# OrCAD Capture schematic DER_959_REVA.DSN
size B; title: DER-959; rev: A
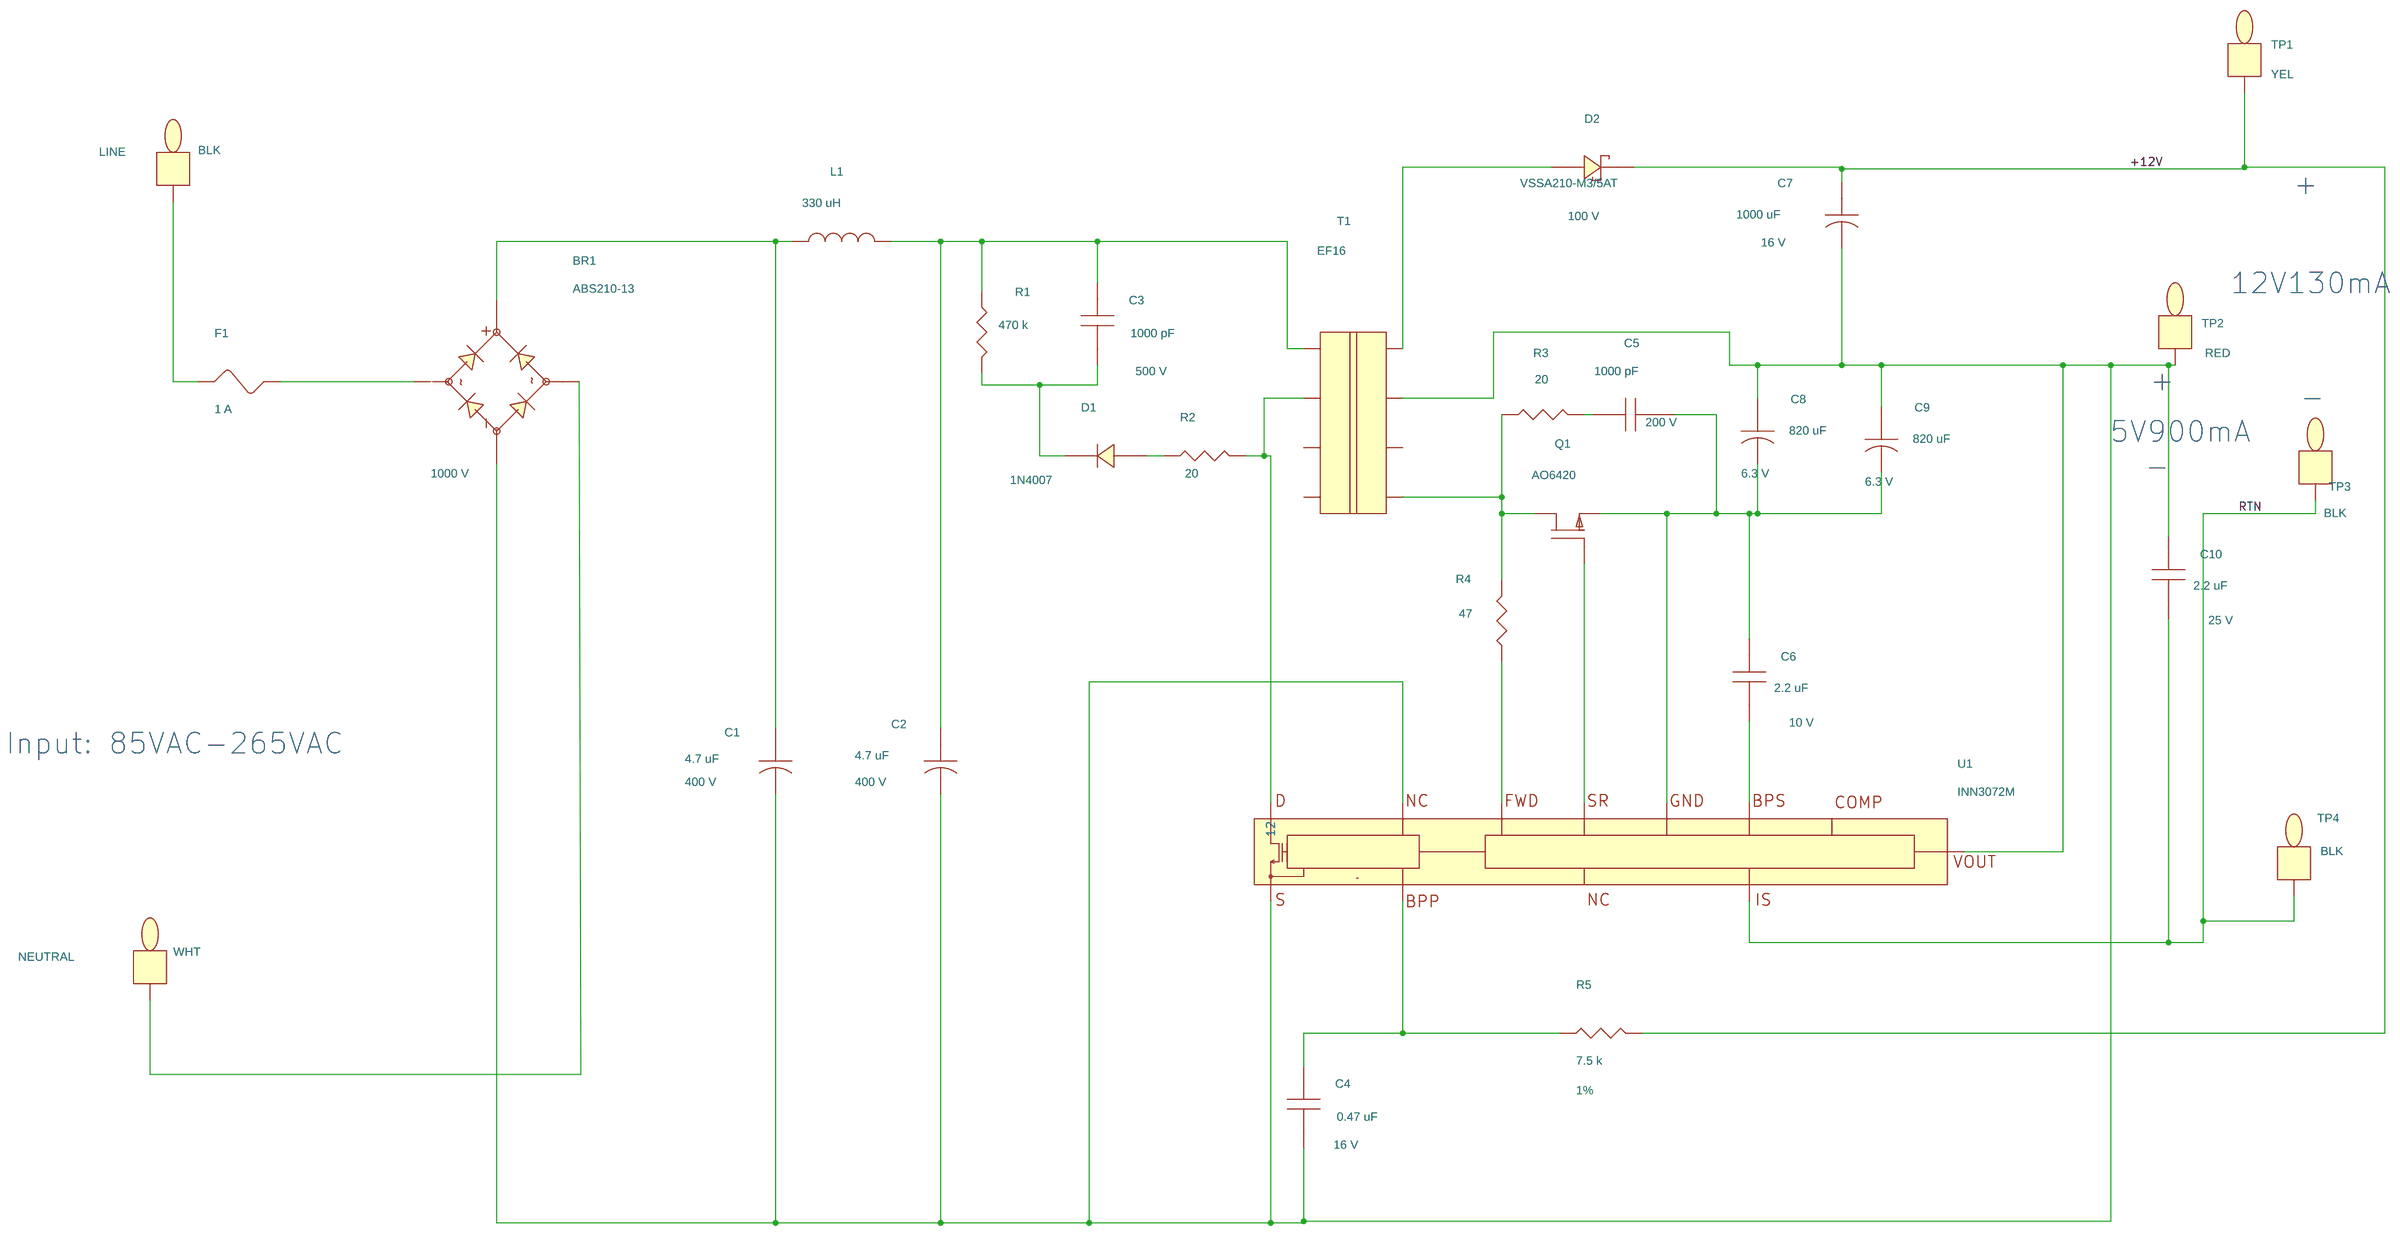
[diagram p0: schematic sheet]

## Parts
BR1  ABS210-13  [pismd_SOPA-4]
C1  4.7 uF  [pipolcapclyd320ls140030]
C2  4.7 uF  [pipolcapclyd320ls140030]
C3  1000 pF  [pismc0805]
C4  0.47 uF  [pismc0603]
C5  1000 pF  [pismc0603]
C6  2.2 uF  [pismc0603]
C7  1000 uF  [pipolcapclyd320ls140030]
C8  820 uF  [pi_polcap_d320ls200d030]
C9  820 uF  [pi_polcap_d320ls200d030]
C10  2.2 uF  [pismc0805]
D1  1N4007  [pidv200x110x040do41]
D2  VSSA210-M3/5AT  [pismdo214ac12]
F1  1 A  [pi_rst_microfuse]
L1  330 uH  [pichoketokinvd216h413ls098d030]
LINE  BLK  [pitpkeystone100x100]
NEUTRAL  WHT  [pitpkeystone100x100]
Q1  AO6420  [pismsot236_short1256]
R1  470 k  [pismr0805]
R2  20  [pismr0805]
R3  20  [pismr0603]
R4  47  [pismr0603]
R5  7.5 k  [pismr0603]
T1  EF16  [pibobbinEF16V8P]
TP1  YEL  [pitpkeystone100x100]
TP2  RED  [pitpkeystone100x100]
TP3  BLK  [pitpkeystone100x100]
TP4  BLK  [pitpkeystone100x100]
U1  INN3072M  [PI_SM_MinSOP16A_1]

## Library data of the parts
BR1 = DIODE_BRIDGE_+~~-: ALT_SYMBOLS: pismd_SOPA-4a,pi_sm_soic4_slot; Disp_Voltage: 1000 V; FPLIST: pismd_SOPA-4,pismd_SOPA-4a,pi_sm_soic4_slot; Part Number: 15-01254-00
C1 C2 = CAP_POL: ALT_SYMBOLS: pipolcapclyd320ls140030h; Disp_Voltage: 400 V; FPLIST: pipolcapclyd320ls140030,pipolcapclyd320ls140030430h,pipolcapclyd320ls140030h; Part Number: 20-00567-00; Voltage: 400 V
C3 = CAP_NP: Disp_Voltage: 500 V; Part Number: 20-09036-00; Voltage: 500 V
C4 = CAP_NP: Disp_Voltage: 16 V; Part Number: 20-08990-00; Voltage: 16 V
C5 = CAP_NP: Disp_Voltage: 200 V; Part Number: 20-09194-00; Voltage: 200 V
C6 = CAP_NP: ALT_SYMBOLS: pismc0603_1; Disp_Voltage: 10 V; FPLIST: pismc0603,pismc0603_1; Part Number: 20-08740-00; Voltage: 10V
C7 = CAP_POL: ALT_SYMBOLS: pipolcapclyd320ls140d30h750; Disp_Voltage: 16 V; FPLIST: pipolcapclyd320ls140030,pipolcapclyd320ls140d30h750; Part Number: 20-08710-00; Voltage: 16 V
C8 C9 = CAP_POL: Disp_Voltage: 6.3 V; Part Number: 20-01648-00; Voltage: 6.3 V
C10 = CAP_NP: Disp_Voltage: 25 V; Part Number: 20-01429-00; Voltage: 25 V
D1 = DIODE: ALT_SYMBOLS: pidax475x125040do41,pidv200x110x040do41wbead,pidax390x125040do41; FPLIST: pidv200x110x040do41,pidax475x125040do41,pidv200x110x040do41wbead,pidax390x125040do41; Part Number: 15-00623-00
D2 = DIODE_SCHOTTKY: Disp_Voltage: 100 V; Part Number: 15-01759-00
F1 = FUSE: ALT_SYMBOLS: pirstmicrofusehoz; FPLIST: pi_rst_microfuse,pirstmicrofusehoz; Part Number: 40-00053-00
L1 = INDUCTOR: Part Number: 30-00073-00
LINE TP3 TP4 = TESTPOINT: ALT_SYMBOLS: TP_TH_CR2_D1_1; FPLIST: pitpkeystone100x100,TP_TH_CR2_D1_1; Part Number: 35-00079-00
NEUTRAL = TESTPOINT: Part Number: 35-00081-00
Q1 = FET_N_DGS: Part Number: 50-00166-00
R1 = R: Part Number: 05-01583-00
R2 = R: Part Number: 05-01478-00
R3 = R: Part Number: 05-01647-00
R4 = R: ALT_SYMBOLS: pismr0603_1; FPLIST: pismr0603,pismr0603_1; Part Number: 05-01656-00
R5 = R: Disp_Tol: 1%; Part Number: 05-01162-00
T1 = BEF16_8PINS_GENERIC: Part Number: 25-01138-00
TP1 = TESTPOINT: ALT_SYMBOLS: TP_TH_CR2_D1_1; FPLIST: pitpkeystone100x100,TP_TH_CR2_D1_1; Part Number: 35-00404-00
TP2 = TESTPOINT: Part Number: 35-00080-00
U1 = Inno3TNMinSOP16_2: Part Number: 10-01311-00

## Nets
+12V: C7.1 D2.1 R5.2 TP1.1
3: U1.3
8: U1.8
RTN: C10.2 TP3.1 TP4.1 U1.1
N12175216: F1.2 LINE.1
N12175256: BR1.1 C1.1 L1.1
N12175292: C2.1 C3.1 L1.2 R1.1 T1.1
N12175504: C3.2 D1.1 R1.2
N12175524: BR1.4 C1.2 C2.2 C4.2 C7.2 C8.1 C9.1 C10.1 T1.7 TP2.1 U1.6 U1.9 U1.11
N12175646: Q1.1(D) R3.1 R4.1 T1.5
N12175650: C5.1 R3.2
N12175654: C5.2 C6.1 C8.2 C9.2 Q1.4(S) U1.2
N12175712: D1.2 R2.1
N12175716: R2.2 T1.2 U1.16(12)
N12175890: Q1.3(G) U1.5
N12175950: BR1.3 NEUTRAL.1
N12175954: C6.2 U1.4
N12176066: C4.1 R5.1 U1.10
N12179234: R4.2 U1.7
N12183686: D2.2 T1.8
N12199280: BR1.2 F1.1

Not connected (* = marked no-connect by the designer): T1 3 4 6

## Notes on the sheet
- +
- 12V130mA
- +
- -
- 5V900mA
- -
- Input: 85VAC-265VAC
